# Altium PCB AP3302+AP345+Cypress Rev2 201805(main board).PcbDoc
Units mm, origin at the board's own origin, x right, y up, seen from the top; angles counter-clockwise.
Board outline 82.15 x 56.7 mm, 2 copper layers (Top Layer, Bottom Layer); 46 components, 60 nets, 128 pads, 78 vias.
Unrouted connection lines stored in the file: 2.
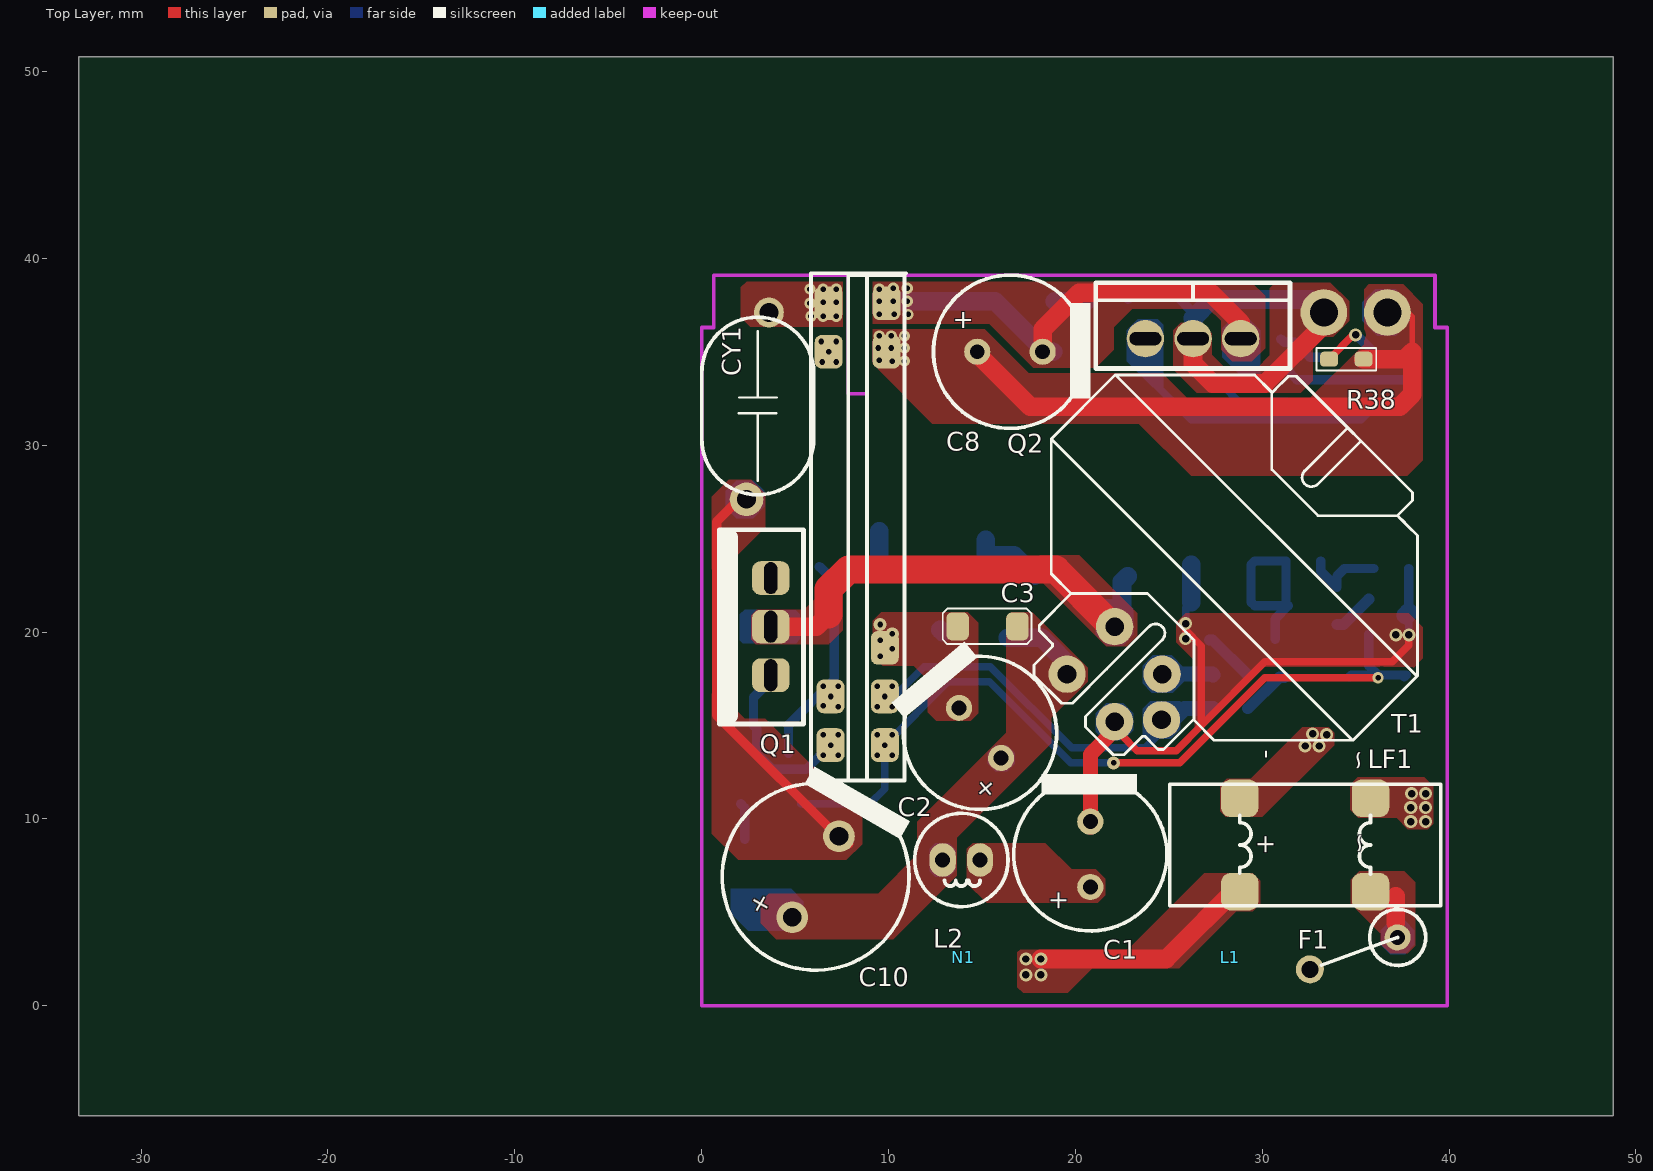
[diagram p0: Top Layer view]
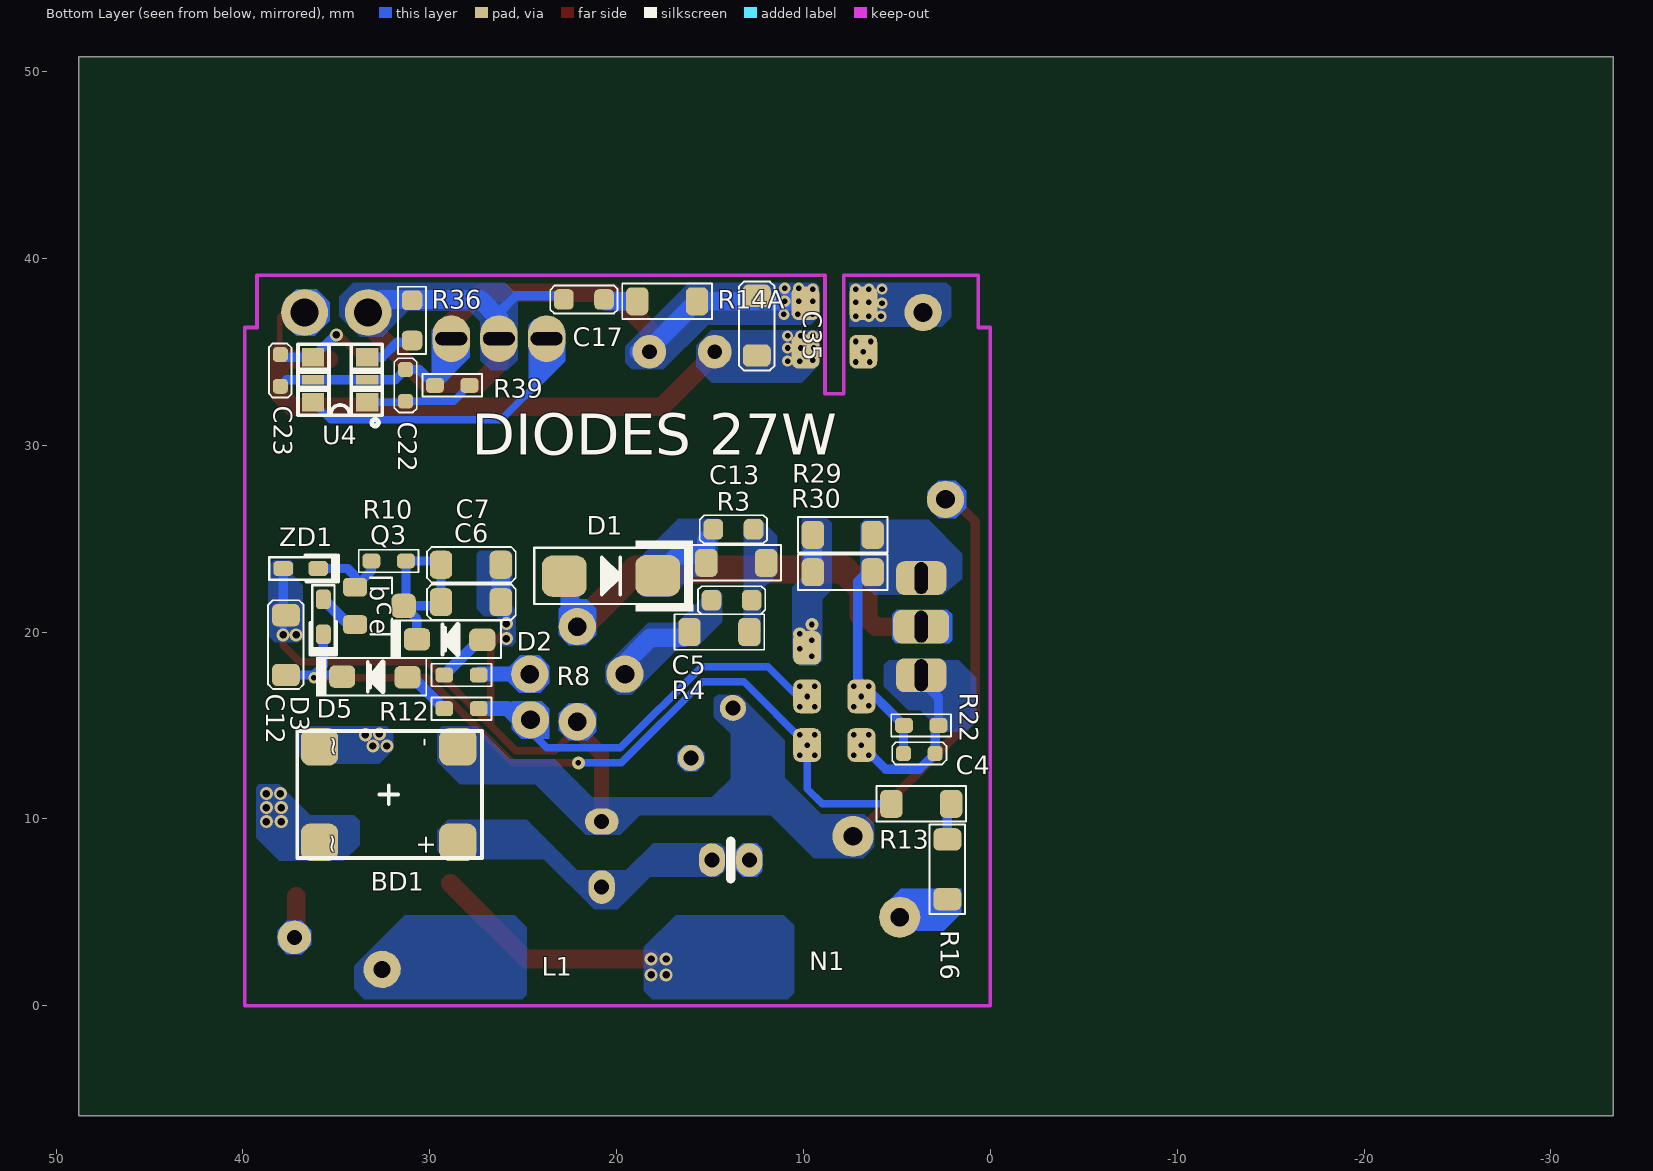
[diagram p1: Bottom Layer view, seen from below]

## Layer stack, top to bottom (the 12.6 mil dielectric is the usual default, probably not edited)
Top Layer: signal copper 0.0356
Dielectric: core 0.32, FR-4, Dk 4.8
Bottom Layer: signal copper 0.0356

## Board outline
-33.35,-5.9 -33.35,50.8 48.8,50.8 48.8,-5.9

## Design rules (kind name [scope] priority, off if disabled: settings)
Clearance [All] p1: gap=0.2
ComponentClearance [All] p1: gap=0.254 collisioncheckmode=3 verticalgap=0.254
PlaneConnect [All] p1: planeconnectstyle=Direct reliefexpansion=0.508 reliefentries=4 reliefconductorwidth=0.254 reliefairgap=0.254
PolygonConnect [All] p1: connectstyle=Direct reliefconductorwidth=0.254 reliefentries=4 polygonreliefangle="90 Angle"
RoomDefinition "AP3302+AP345+WT6615F Rev4 20170908(S2)updated" [InComponentClass('AP3302+AP345+WT6615F Rev4 20170908(S2)updated')] p1: confinementstyle=ConfineIn formatcopy=TRUE lockcomponents=FALSE outline -487.457,-410.573 -436.657,-410.573 -436.657,-385.173 -487.457,-385.173
RoutingVias [All] p1: holewidth=0.711 width=1.27 viastyle="Through Hole" minholewidth=0.711 minwidth=1.27 maxholewidth=0.711 maxwidth=1.27
SolderMaskExpansion [All] p1: expansion=0.102
TestPointUsage [All] p1: valid=0 allowmultiple=FALSE
Testpoint [(IsPad And (OnTopLayer Or OnBottomLayer))] p1: side=3 testpointundercomponent=TRUE minsize=1.016 maxsize=2.54 preferedsize=1.524 minholesize=0 maxholesize=1.016 preferedholesize=0.813 testpointgrid=0.025 style=297 order=0-112345678
Width [All] p1: maxlimit=3 minlimit=0.2 preferedwidth=0.3
17 further rules are at their usual default settings.

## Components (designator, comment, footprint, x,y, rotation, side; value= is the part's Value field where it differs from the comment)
BD1 "MSB30KH" BD-MSBL2A_6.7*7.4 32.2,11.3 r270 bottom
C1 "15uF/400V" EC-8X16-P3.5-C#1 20.8,8.1 r90 top
C2 "15uF/400V" EC-8X16-P3.5-C#2 14.9,14.6 r130 top
C3 "10nF/630V" 1206C(W) 15.3,20.3 r0 top
C4 "100pF/50V" 0603C(W) 3.8,13.5 r180 bottom
C5 "2.2nF/250V" 0805C(W) 13.9,21.7 r0 bottom
C6 "2.2uF/100V" 1206C(w) 27.8,21.6 r0 bottom
C7 "2.2uF/100V" 1206C(w) 27.8,23.6 r0 bottom
C8 "680uF/16V" EC-8X16-P3.5-C#3 16.5,35 r0 top
C10 "22uF/400V" EC-10X15-P5-C 6.1,6.9 r60 top (schematic designator C1)
C12 "4.7uF/50V" 1206C(W) 37.7,19.3 r270 bottom
C13 "2.2nF/250V" 0805C(W) 13.7,25.5 r180 bottom
C17 "1nF/200v" 0805c(W) 21.7,37.8 r180 bottom
C22 "22nF/50v" 0603c(w) 31.3,33.2 r270 bottom
C23 "100nF/50v" 0603C(W) 38,34 r90 bottom
C35 "10uF/16V" 1206C(w) 12.5,36.4 r90 bottom (schematic designator C7)
CY1 "470pF Y1" YC-9.5X6-P10 3,32.1 r270 top
D1 "RS1M" SMD-(DO-214AC/SMA) 20.3,23 r270 bottom
D2 "RS1MSWF" SMD-(SOD-123) 28.9,19.6 r180 bottom
D3 "1N4148WS" SMD-(SOD-523) 35.7,20.8 r90 bottom
D5 "RS1MSWF" SMD-(SOD-123) 32.9,17.6 r180 bottom
F1 "T2AL/250VAC" F-7.2X2.7-P5 34.9,2.8 r200 top
L1 "L" 22#单线打端子 28.3,2.6 r0 top
L2 "220uH" L-D5-P2 13.9,7.8 r180 top
LF1 "2mH" LF-14.5X6.5-P7X5 32.3,8.6 r180 top
N1 "N" 22#单线打端子 14,2.6 r0 top
Q1 "DMJ65H650SCTI" TO-220-T型槽 3.7,20.2 r180 top
Q2 "DMTH10H010LCT" TO-220(DH) 26.3,35.7 r180 top
Q3 "DMN24H3D" sot-23-1 32.6,21.4 r270 bottom
R3 "100K" 1206(W) 13.6,23.7 r0 bottom
R4 "100K" 1206(W) 14.5,20 r180 bottom
R8 "2R" 0603(W) 28.3,17.7 r180 bottom
R10 "100K" 0603(w) 32.2,23.8 r0 bottom
R12 "2R" 0603(W) 28.3,15.9 r0 bottom
R13 "1.8M" 1206(W) 3.7,10.8 r180 bottom
R14A "51R" 1206(w) 17.3,37.7 r0 bottom
R16 "1.8M" 1206(W) 2.3,7.3 r270 bottom
R22 "47K" 0603(W) 3.7,15 r180 bottom
R29 "0.82R" 1206(W) 7.9,25.2 r180 bottom
R30 "0.82R" 1206(W) 7.9,23.2 r180 bottom
R36 "10R" 0805(w) 31,36.6 r270 bottom
R38 "10R" 0603(W) 34.5,34.6 r180 top
R39 "51K" 0603(w) 28.8,33.2 r180 bottom
T1 "TRANS-RM8" TF-RM8(PIN6+2) 28.5,24 r45 top locked
U4 "APR345" SOT-23-6 34.8,33.5 r0 bottom
ZD1 "20V" SMD-(SOD-523) 36.9,23.4 r0 bottom

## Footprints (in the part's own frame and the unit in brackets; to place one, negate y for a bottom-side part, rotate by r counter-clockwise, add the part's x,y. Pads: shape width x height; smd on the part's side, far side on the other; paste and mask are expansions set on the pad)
22#单线打端子 [mm]
0603(W) [mm]
  rrect50% 0.95x0.8 smd mask+0.03: 1(-0.925,0) 2(0.925,0)
  silkscreen extent -1.6,-0.6 1.6,0.6, body extent -0.77,-0.42 0.78,0.43, height 0.45
0603(w) [mm]
  rrect50% 0.95x0.8 smd mask+0.03: 1(-0.925,0) 2(0.925,0)
  silkscreen extent -1.6,-0.6 1.6,0.6, body extent -0.77,-0.42 0.78,0.43, height 0.45
0603C(W) [mm]
  rrect50% 0.8x0.8 smd mask+0.03: 1(-0.85,0) 2(0.85,0)
  silkscreen extent -1.45,-0.6 1.45,0.6, body extent -0.8,-0.45 0.8,0.4, height 0.8
0603c(w) [mm]
  rrect50% 0.8x0.8 smd mask+0.03: 1(-0.85,0) 2(0.85,0)
  silkscreen extent -1.45,-0.6 1.45,0.6, body extent -0.8,-0.45 0.8,0.4, height 0.8
0805(w) [mm]
  rrect50% 1.05x1.1 smd mask+0.03: 1(-1.15,0.05) 2(1,0.05)
  silkscreen extent -1.88,-0.7 1.72,0.8, body extent -1.07,-0.57 0.93,0.68, height 0.45
0805C(W) [mm]
  rrect50% 1.05x1.1 smd mask+0.03: 1(-1.125,0) 2(1.025,0)
  silkscreen extent -1.85,-0.75 1.75,0.75, body extent -1.05,-0.62 0.95,0.63, height 0.6
0805c(W) [mm]
  rrect50% 1.05x1.1 smd mask+0.03: 1(-1.125,0) 2(1.025,0)
  silkscreen extent -1.85,-0.75 1.75,0.75, body extent -1.05,-0.62 0.95,0.63, height 0.6
1206(W) [mm]
  rrect50% 1.2x1.5 smd mask+0.03: 1(-1.6,0) 2(1.6,0)
  silkscreen extent -2.4,-0.95 2.4,0.95, body extent -1.6,-0.8 1.6,0.8, height 0.55
1206(w) [mm]
  rrect50% 1.2x1.5 smd mask+0.03: 1(-1.6,0) 2(1.6,0)
  silkscreen extent -2.4,-0.95 2.4,0.95, body extent -1.6,-0.8 1.6,0.8, height 0.55
1206C(W) [mm]
  rrect50% 1.2x1.5 smd mask+0.03: 1(-1.6,0) 2(1.6,0)
  silkscreen extent -2.4,-0.95 2.35,0.95, body extent -1.6,-0.8 1.6,0.8, height 0.79
1206C(w) [mm]
  rrect50% 1.2x1.5 smd mask+0.03: 1(-1.6,0) 2(1.6,0)
  silkscreen extent -2.4,-0.95 2.35,0.95, body extent -1.6,-0.8 1.6,0.8, height 0.79
BD-MSBL2A_6.7*7.4 [mm]
  rrect50% 2x2 smd: 1(2.55,3.7) 2(2.55,-3.7) 3(-2.55,-3.7) 4(-2.55,3.7)
  silkscreen extent -3.4,-4.9 3.4,5
EC-8X16-P3.5-C#1 [mm]
  round 1.4 / inner oval 1.8x1.4 / far side oval 1.8x1.4 hole 0.8: 1(-1.75,0)
  round 1.4 / inner oval 1.4x1.8 / far side oval 1.4x1.8 hole 0.8: 2(1.75,0)
  silkscreen extent -4.1,-4.1 4.3,4.1
EC-8X16-P3.5-C#2 [mm]
  round 1.4 hole 0.8: 1(-1.75,0) 2(1.75,0)
  silkscreen extent -4.1,-4.1 4.3,4.1
EC-8X16-P3.5-C#3 [mm]
  round 1.4 / inner round 1.8 / far side round 1.8 hole 0.8: 1(-1.75,0) 2(1.75,0)
  silkscreen extent -4.1,-4.1 4.3,4.1
EC-10X15-P5-C [mm]
  round 1.7 / inner round 2.2 / far side round 2.2 hole 1: 1(-2.5,0) 2(2.5,0)
  silkscreen extent -5,-5 5.1,5
F-7.2X2.7-P5 [mm]
  round 1.4 / inner round 1.8 / far side round 1.8 hole 0.8: 1(-2.5,0)
  round 1.5 / inner round 2 / far side round 2 hole 0.9: 2(2.5,0)
  silkscreen extent -4,-1.5 1.85,1.5
L-D5-P2 [mm]
  oval 1.4x1.8 hole 0.8: 1(-1,0) 2(1,0)
  silkscreen extent -2.5,-2.5 2.5,2.5
LF-14.5X6.5-P7X5 [mm]
  rrect50% 2x2 smd: 1(-3.5,2.5) 2(-3.5,-2.5) 3(3.5,-2.5) 4(3.5,2.5)
  silkscreen extent -7.25,-3.25 7.25,3.25
SMD-(DO-214AC/SMA) [mm]
  rrect50% 2.2x2.4 smd: 1(0.013,-2.5) 2(-0.013,2.5)
  silkscreen extent -1.9,-4.1 1.91,4.4
SMD-(SOD-123) [mm]
  rrect50% 1.4x1.2 smd mask+0.03: 1(1.71,-0.02) 2(-1.79,0.01)
  silkscreen extent -3.2,-1.04 2.71,1.06, body extent -1.89,-0.79 1.81,0.81, height 1.2
SMD-(SOD-523) [mm]
  rrect50% 1.05x0.8 smd: 1(0.95,0) 2(-0.925,0)
  silkscreen extent -2,-0.7 1.7,0.7
sot-23-1 [mm]
  rrect50% 1x1.3 smd: 1(-1,-1.4) 3(1,-1.4)
  rrect50% 1.3x1.3 smd: 2(0,1.2)
  silkscreen extent -1.5,-0.6 1.53,0.58
SOT-23-6 [mm]
  rect 1.2x1 smd: 1(-1.45,1.2) 3(-1.45,-1.2) 4(1.45,-1.2) 6(1.45,1.2)
  rect 1.2x0.5 smd: 2(-1.45,0) 5(1.45,0)
  silkscreen extent -2.3,-1.9 2.25,2.48
TF-RM8(PIN6+2) [mm]
  round 2 hole 1: 1(-10.75,1.9) 2(-10.75,-1.7) 4(-8.9,-3.4) 5(-7.15,1.9) 6(-7.15,-1.7)
  round 2.5 hole 1.5: 7(12.657,5.869) 8(15.061,3.465)
  silkscreen extent -12.05,-11.42 9.2,11.4
TO-220(DH) [mm]
  round 2 / inner oval 2x2.5 / far side oval 2x2.5 hole 0.7 slot 1.7 at 0 deg: 1(2.55,0) 2(0,0) 3(-2.55,0)
  silkscreen extent -5.19,-3 5.21,1.6
TO-220-T型槽 [mm]
  rrect50% 2x1.8 / inner rrect50% 2.7x1.8 / far side rrect50% 2.7x1.8 hole 0.7 slot 1.7 at 90 deg: 1(0,2.512) 3(0,-2.687)
  round 2 on Bottom Solder: 1(0,-3.537) 2(0.025,3.538)
  round 1 on Bottom Solder: 2(-1.4,-2.962) 5(1.397,-3.008) 6(-1.524,2.834) 10(1.524,2.834)
  rrect50% 2x1.8 / inner rrect50% 2x1.8 / far side rrect50% 3x1.8 hole 0.7 slot 1.7 at 90 deg: 2(0,-0.087)
  silkscreen extent -1.75,-5.28 2.75,5.12
YC-9.5X6-P10 [mm]
  round 1.6 / inner round 2 / far side round 2 hole 1: 1(-5,0.6)
  round 1.8 / inner round 2 / far side round 2 hole 1: 2(5,-0.6)
  silkscreen extent -4.75,-3 4.75,3

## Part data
BD1: library part BRIDGE, "Diode"
C1 C2 C10: library part "Cap Pol1", "Polarized Capacitor (Radial)"
C3 C4 C5 C6 C7 C12 C13 C23 C35 CY1: library part Cap, "Capacitor"
C8: library part CAPACITOR, "Capacitor"
C17 C22: library part CAP, "Capacitor"
D1 D2 D3 D5: library part D, "Diode"
F1: library part "Fuse 2", "Fuse"
L1 N1: library part CON1, "Connector"
L2: library part INDUCTOR, "inductor"
LF1: library part "INDUCTOR IRON"
Q1 Q2: library part "MOSFET N"
Q3: library part MOS-N2, "MOS"
R3 R4 R8 R10 R12 R13 R16 R22 R29 R30: library part Res3, "Resistor"
R14A R36 R38 R39: library part RES2
T1: library part TRANS_RM7, "transformer"
U4: library part AP345
ZD1: library part ZD, "Zener Diode"

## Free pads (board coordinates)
  rrect50% 1.5x1.8 smd: 5(6.8,35) 5(6.8,37.6) 5(6.9,16.55) 5(6.9,13.95) 5(9.8,13.95) 5(9.8,16.55) 5(9.8,19.15) 5(9.9,35) 5(9.9,37.6)
  rrect50% 1.5x1.8 smd far side: 5(6.8,35) 5(6.8,37.6) 5(6.9,13.95) 5(6.9,16.55) 5(9.8,13.95) 5(9.8,16.55) 5(9.8,19.15) 5(9.9,35) 5(9.9,37.6)

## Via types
v1: diameter 0.6, hole 0.3, Top Layer to Bottom Layer, 53 vias
v2: diameter 0.7, hole 0.4, Top Layer to Bottom Layer, 19 vias
v3: diameter 0.7, hole 0.3, Top Layer to Bottom Layer, 6 vias

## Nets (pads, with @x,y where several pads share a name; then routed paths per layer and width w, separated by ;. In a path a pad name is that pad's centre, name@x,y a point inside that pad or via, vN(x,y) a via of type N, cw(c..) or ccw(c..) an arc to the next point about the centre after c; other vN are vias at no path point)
CC1: 
CC2: 
D+: 
D-: 
EARTH: 
GND: BD1.4 C1.2 C2.2 C3.1 C6.1 C7.1 C10.2 C12.1 CY1.2 pad.5@9.8,19.15 R29.1 R30.1 T1.2 ZD1.1 | length 62.6
  Top Layer w0.4: T1.2@22.401,15.297 T1.2@22.501,15.397 ; T1.2@22.501,14.449 23.3,13.65 25.395,13.65 26.75,15.005 ; v2(25.9,20.45) 25.9,20.1 26.75,19.25 26.75,15.005 ; v2(37.85,19.85) 37.85,19.3 36.95,18.4 30.145,18.4 26.75,15.005
  Top Layer w0.5: CY1.2@2.4,27.5 0.8,25.9 0.8,15.55 7.682,8.668 C10.2@7.868,8.668
  Top Layer w0.8: C1.2@20.8,9.55 20.8,13.45 22.501,15.151 T1.2@22.501,15.197
  Bottom Layer w0.4: v2(25.9,20.45) 25.9,21.3 C6.1 ; C12.1 37.85,20.75 v2(37.85,19.85)
  Bottom Layer w0.5: C12.1@37.85,21.05 37.85,22.1 ZD1.1
  Bottom Layer w1: CY1.2@2.4,27.5 CY1.2@2.65,27.25 ; R30.1@9.5,23.5 R29.1@9.5,25.4 ; C6.1 C7.1 ; C12.1 C12.1@37.85,21.05
  other v2: 25.9,19.65 37.15,19.85
  other v3: 9.55,18.7 10.2,19.1 9.55,19.55 10.2,19.9 9.55,20.4
NetBD1_1: BD1.1 C1.1 L2.1 | length 0.1
  Top Layer w0.5: L2.1@14.783,7.8 L2.1
NetBD1_2: BD1.2 LF1.2
  other v2: 37.95,9.85 38.75,9.85 37.95,10.6 38.75,10.6 38,11.35 38.75,11.35
NetBD1_3: BD1.3 LF1.3
  other v2: 32.3,13.9 33.05,13.9 33.45,14.5 32.7,14.55
NetC2_1: C2.1 C3.2 C5.2 C10.1 L2.2 R4.1 R16.2 T1.1 | length 4.6
  Bottom Layer w0.254: T1.1@19.4,17.9 T1.1@19.75,17.9
  Bottom Layer w1: R4.1@16.4,19.7 18.197,19.7 T1.1@19.955,17.942
NetC4_1: C4.1 pad.5@6.9,16.55 Q1.3 R22.1 R29.2 R30.2 | length 11.4
  Bottom Layer w0.5: C4.1 4.65,14.975 R22.1 7.1,17.475 7.1,22.7 R30.2@6.3,23.5
  other v1: 7.3,16 6.5,16.05 6.9,16.55 6.5,17.1 7.3,17.1
NetC4_2: C4.2 pad.5@6.9,13.95 Q1.1@3.7,17.688 R22.2 | length 9.7
  Bottom Layer w0.5: Q1.1@3.962,17.688 3.7,17.688 3.7,17.425 2.775,16.5 R22.2 2.95,14.825 C4.2 3.8,12.65 5.6,12.65 v1(6.9,13.95)
  other v1: 6.5,13.4 7.3,13.4 6.5,14.5 7.3,14.5
NetC5_1: C5.1 C13.2 R3.1 R4.2 | length 0.2
  Bottom Layer w1: R4.2@12.775,20.125 R4.2
NetC6_2: C6.2 C7.2 D2.2 Q3.2 R10.1 | length 10.6
  Bottom Layer w0.5: D2.2 30.69,20.69 Q3.2 ; Q3.2 31.275,21.525 R10.1 29.6,23.8 C7.2 C6.2 29.6,21.4 Q3.2
NetC13_1: C13.1 D1.2 R3.2 | length 3.9
  Bottom Layer w1: 15.2,24.925 15.2,24.1 16.713,24.1 D1.2
NetC15_1: 
NetC15_2: 
NetC16_1: 
NetC16_2: 
NetC17_1: C17.1 Q2.2 R36.1 T1.7 | length 23.8
  Top Layer w1: Q2.2@26.3,35.5 26.3,34.35 27.35,33.3 30.15,33.3 33.3,36.45 T1.7
  Bottom Layer w0.5: C17.1 23.025,38 25.4,38 26.3,37.1 26.3,36.8 Q2.2@26.3,35.5
  Bottom Layer w1: Q2.2@26.3,36.8 27.3,37.8 32.6,37.8 T1.7
NetC17_2: C17.2 R14A.2 | length 2.1
  Bottom Layer w0.4: C17.2 C17.2@20.9,37.575
  Bottom Layer w1: R14A.2 20.575,37.7 C17.2
NetC18_1: 
NetC19_2: 
NetC22_2: C22.2 R39.2 U4.1 | length 5.9
  Bottom Layer w0.4: R39.2@27.97,33.2 R39.2 28.725,32.35 C22.2 31.35,32.3 U4.1
NetC23_2: C23.2 R38.2 U4.4 | length 5.4
  Top Layer w0.4: R38.2 v2@34.875,35.9
  Bottom Layer w0.5: v2(35,35.9) 35.05,35.9 U4.4 37.85,34.7 C23.2
NetC24_2: 
NetC26_2: 
NetC28_1: 
NetC29_2: 
NetC30_2: 
NetC31_2: 
NetD1_1: D1.1 Q1.2@3.7,20.287 T1.5 | length 24
  Top Layer w1: Q1.2@3.7,20.287 6.137,20.287 6.8,20.95
  Top Layer w1.5: 6.8,20.95 6.8,22.3 7.85,23.35 18.95,23.35 T1.5@21.812,20.488
  Bottom Layer w1: T1.5@22.501,20.488 22.501,22.688 D1.1
NetD2_1: D2.1 R8.1 | length 2.8
  Bottom Layer w0.6: D2.1 27.345,19.58 R8.1
NetD3_1: D3.1 Q3.3 | length 2.3
  Bottom Layer w0.6: Q3.3 34.35,20.4 D3.1
NetD4_2: 
NetD5_1: D5.1 R12.2 | length 2.7
  Bottom Layer w0.6: R12.2 29.247,15.9 30.927,17.58 D5.1
NetD6_1: 
NetD6_2: 
NetF1_1: F1.1 LF1.1 | length 1.4
  Top Layer w1: 37.148,4.434 37.148,5.852
NetF1_2: F1.2
NetLF1_4: LF1.4 | length 12.4
  Top Layer w1: v2(18.15,2.5) 24.85,2.5 LF1.4@28.9,6.55
  other v2: 17.35,1.65 18.15,1.65 17.35,2.5
NetNTC1_1: 
NetNTC2_1: 
NetQ2_1: Q2.1 U4.6 | length 15.6
  Bottom Layer w0.4: Q2.1@23.75,35.5 23.75,33.8 26.19,31.36 35.31,31.36 U4.6
NetQ3_1: Q3.1 R10.2 ZD1.2 | length 4.5
  Bottom Layer w0.5: R10.2 33.125,23.275 Q3.1 34,23 34.4,23.4 ZD1.2
NetQ4_1: 
NetQ4_4: 
NetR1_2: 
NetR8_2: R8.2 T1.6 | length 2.7
  Bottom Layer w0.8: T1.6 27.333,17.742 R8.2
NetR12_1: pad.5@9.8,16.55 R12.1 T1.4 | length 20.9
  Bottom Layer w0.4: v1(9.8,16.55) 10.3,16.55 11.9,18.15 15.45,18.15 19.803,13.797 23.744,13.797 T1.4@25.25,15.303
  Bottom Layer w0.8: T1.4@25.25,15.303 25.847,15.9 R12.1
  other v1: 9.4,16 10.2,16 9.4,17.1 10.2,17.1
NetR13_2: R13.2 R16.1 | length 2
  Bottom Layer w0.5: R13.2 2.3,10.6 R16.1
NetR18_2: 
NetR25_2: 
NetR27_1: 
NetR31_2: 
NetR36_2: R36.2 U4.3 | length 2.8
  Bottom Layer w0.5: R36.2@31,35.675 31.175,35.5 31.75,35.5 32.55,34.7 U4.3
OP+: C8.1 C35.1 pad.5@6.8,35 pad.5@9.9,35 R38.1 T1.8 | length 32.3
  Top Layer w0.3: T1.8@37.6,37.3 38.025,36.875 38.025,35
  Top Layer w1: C8.1@14.7,34.95 17.59,32.06 37.36,32.06 38.025,32.725 38.025,35 37.625,34.6 R38.1
  other v1: 6.45,34.45 7.2,34.45 10.2,34.5 10.85,34.5 9.5,34.55 6.8,35 9.45,35.2 10.15,35.2 10.85,35.2 6.4,35.55 7.2,35.55 9.5,35.85 10.15,35.85 10.85,35.85
SGND: C8.2 C22.1 C23.1 C35.2 CY1.1 pad.5@6.8,37.6 pad.5@9.9,37.6 Q2.3 R14A.1 R39.1 U4.2 U4.5 | length 35.5
  Top Layer w1: C8.2 18.25,36.2 20.2,38.15 27.25,38.15 28.85,36.55 Q2.3@28.85,35.9
  Bottom Layer w0.5: Q2.3@28.85,35.5 29.1,35.25 29.1,33.825 R39.1 30.575,34.05 C22.1 31.85,33.5 U4.2 U4.5 37.65,33.5 C23.1
  Bottom Layer w1: pad.5@10.1,37.7 R14A.1 18.25,35.15 C8.2 C8.2@18.8,35
  other v1: 5.85,36.9 6.5,36.9 7.2,36.9 9.5,37 10.3,37 11.05,37 5.8,37.6 6.5,37.65 7.2,37.65 9.5,37.7 10.25,37.7 11,37.7 5.8,38.35 6.5,38.35 7.2,38.35 9.5,38.35 10.25,38.4 11,38.4
VCC: C12.2 D3.2 D5.2 pad.5@9.8,13.95 R13.1 | length 44.2
  Top Layer w0.4: v3(22.05,13) 25.593,13 30.143,17.55 v1(36.2,17.55)
  Bottom Layer w0.4: R13.1 9,10.8 9.8,11.6 v1(9.8,13.95) 13.2,17.35 15.401,17.35 19.751,13 v3(22.05,13)
  Bottom Layer w0.5: D5.2 34.78,17.7 v1@36.2,17.7 ; D3.2 35.7,18.2 v1@36.2,17.7 ; C12.2@37.61,17.61 C12.2 v1@36.2,17.7
  other v1: 9.4,13.4 10.2,13.4 9.4,14.5 10.2,14.5
VOUT: 
pads on no net: Q1.1@3.7,23.737 Q1.2@3.675,16.662 Q1.2@5.1,23.162 Q1.5 Q1.6 Q1.10

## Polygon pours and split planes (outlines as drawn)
SGND on Top Layer "MidLayer2-No Net" (solid, remove dead copper, pour order 1000): 9.1,38.75 24,38.75 24,38.25 22.05,36.323 22.05,35.1 21.1,34.15 17.75,34.15 15.4,36.5 9.1,36.5
OP+ on Top Layer "MidLayer2-No Net" (solid, remove dead copper, pour order 1001): 35.7,38.6 37.55,38.6 38.6,37.55 38.6,29.2 37.75,28.35 26.2,28.35 23.4,31.15 12.35,31.15 9.1,34.4 9.1,36.2 15.15,36.2 17.5,33.85 24.65,33.85 26.1,32.4 32.45,32.4 35.45,35.4 35.45,38.35
NetC2_1 on Top Layer "Top Layer-No Net" (solid, pour order 1004): 4,3.55 10.25,3.55 13.65,6.95 13.65,9 18.7,14.05 18.7,15.4 20.65,17.35 20.65,18.1 17.7,21.05 16.55,21.05 16.3,20.8 16.3,14.6 11.55,9.85 11.55,8.1 9.45,6 3.6,6 3.15,5.55 3.15,4.4
NetD1_1 on Top Layer "MidLayer2-No Net" (solid, remove dead copper, pour order 1001): 17.85,23.85 18.1,24.1 20.2,24.1 23.3,21 23.3,19.8 22.75,19.25 21.65,19.25 17.85,23.05
SGND on Top Layer "MidLayer2-No Net" (solid, remove dead copper, pour order 1004): 29.4,38.75 30.15,38 30.15,35.2 29.45,34.5 28.4,34.5 27.8,35.1 27.8,36.65 27.15,37.3 22.1,37.3 22.1,38.7 22.15,38.75
NetD1_1 on Top Layer "MidLayer2-No Net" (solid, remove dead copper, pour order 1002): 5.5,21.2 6.7,22.4 7.55,22.4 7.55,20.1 6.8,19.35 2.9,19.35 2.65,19.6 2.65,20.9 2.95,21.2
SGND on Top Layer "MidLayer2-No Net" (solid, remove dead copper, pour order 1002): 7.6,38.75 7.6,36.35 2.6,36.35 2.1,36.85 2.1,38.45 2.4,38.75
NetBD1_3 on Top Layer "Top Layer-No Net" (solid, pour order 1005): 28.05,10.1 30,10.1 33.85,13.95 33.85,14.6 33.55,14.9 32.15,14.9 29.4,12.15 28.1,12.15 27.75,11.8 27.75,10.4
NetLF1_4 on Top Layer "Top Layer-No Net" (solid, pour order 1002): 17.2,0.7 19.6,0.7 20.9,2 25.55,2 28.6,5.05 29.5,5.05 29.9,5.45 29.9,6.7 29.5,7.1 26.9,7.1 22.8,3 17.05,3 16.9,2.85 16.9,1
NetF1_1 on Top Layer "Top Layer-No Net" (solid, pour order 1000): 34.75,6.75 34.75,5.45 36.35,3.85 36.35,3.3 36.85,2.8 37.8,2.8 38.2,3.2 38.2,6.6 37.6,7.2 35.2,7.2
NetBD1_2 on Top Layer "Top Layer-No Net" (solid, pour order 1001): 35.125,12.225 38.675,12.225 39.15,11.75 39.15,9.75 38.85,9.45 37.8,9.45 37.2,10.05 35.15,10.05 34.725,10.475 34.725,11.825
NetC17_1 on Top Layer "MidLayer2-No Net" (solid, remove dead copper, pour order 1005): 30.7,38.7 33.65,38.7 34.65,37.7 34.65,36.65 33.8,35.8 33.35,35.8 32.7,35.15 32.7,33.45 32.05,32.8 26.5,32.8 25.25,34.05 25.25,36.15 25.65,36.55 26.75,36.55 27.3,36 27.3,34.85 28.05,34.1 29.7,34.1 30.4,34.8 30.4,38.4
NetBD1_1 on Top Layer "Top Layer-No Net" (solid, pour order 1000): 14.5,8.7 18.4,8.7 19.8,7.3 21.1,7.3 21.6,6.8 21.6,5.9 21.2,5.5 15.25,5.5 14.2,6.55 14.2,8.4
GND on Top Layer "MidLayer2-No Net" (solid, remove dead copper, pour order 1000): 25.9,21 37.85,21 38.6,20.25 38.6,18.6 38.1,18.1 38.05,18.15 29.895,18.15 27.095,15.35 26.4,14.65 26.4,18.45 25.4,19.45 25.4,20.5
GND on Top Layer "MidLayer2-No Net" (solid, remove dead copper, pour order 1007): 1.45,28.15 2.65,28.15 3.4,27.4 3.4,25.6 1.15,23.35 0.55,23.35 0.55,27.25
GND on Top Layer "MidLayer2-No Net" (solid, remove dead copper, pour order 1006): 7.75,7.8 8.6,8.65 8.6,10.15 3.4,15.35 2.3,15.35 0.95,16.7 0.55,16.7 0.55,9.2 1.95,7.8
GND on Top Layer "Top Layer-No Net" (solid, pour order 1006): 12.1,17.45 12.1,15.7 12.55,15.25 14.4,15.25 14.8,15.65 14.8,20.5 14.25,21.05 9.6,21.05 9.15,20.6 9.15,18.75 9.7,18.2 11.35,18.2
SGND on Bottom Layer "MidLayer2-No Net" (solid, remove dead copper, pour order 1003): 16.15,38.7 19.55,35.3 19.55,34.4 19.2,34.05 17.5,34.05 15.1,36.45 9.6,36.45 9.05,37 9.05,38.4 9.35,38.7
OP+ on Bottom Layer "MidLayer2-No Net" (solid, remove dead copper, pour order 1005): 14.95,36.15 15.75,35.35 15.75,34.2 14.9,33.35 10.1,33.35 9.1,34.35 9.1,36.15
NetF1_2 on Bottom Layer "Top Layer-No Net" (solid, pour order 1007): 25.05,0.35 33.5,0.35 34.05,0.9 34.05,2.15 31.35,4.85 25.45,4.85 24.8,4.2 24.8,0.6
NetLF1_4 on Bottom Layer "Top Layer-No Net" (solid, pour order 1009): 10.85,0.35 18.1,0.35 18.55,0.8 18.55,3.15 16.85,4.85 11.05,4.85 10.5,4.3 10.5,0.7
NetC4_2 on Bottom Layer "MidLayer2-No Net" (solid, remove dead copper, pour order 1000): 1.7,18.5 5.45,18.5 5.7,18.25 5.7,17.1 4.4,15.8 3.75,15.8 2.6,14.65 1.3,14.65 0.75,15.2 0.75,17.55
NetC2_1 on Bottom Layer "Top Layer-No Net" (solid, pour order 1003): 14.35,22.05 14.35,20.55 15.65,19.25 16.6,19.25 19.2,16.65 19.95,16.65 20.6,17.3 20.6,18.2 18.3,20.5 16.75,20.5 15,22.25 14.55,22.25
GND on Bottom Layer "Top Layer-No Net" (solid, pour order 1015): 29.6,14.7 29.6,13.05 28.4,11.85 24.35,11.85 21.65,9.15 19.8,9.15 18.75,10.2 11.75,10.2 9.45,7.9 6.8,7.9 6.2,8.5 6.2,9.7 6.75,10.25 9.05,10.25 11,12.2 11,14.2 13.45,16.65 14.6,16.65 14.8,16.45 14.8,15.45 13.9,14.55 13.9,12.15 14.9,11.15 21.3,11.15 23.35,13.2 25.75,13.2 27.5,14.95 29.35,14.95
NetC17_1 on Bottom Layer "MidLayer2-No Net" (solid, remove dead copper, pour order 1008): 25.3,38 26,38.7 34.1,38.7 34.85,37.95 34.85,36.9 33.75,35.8 32.55,35.8 31.15,37.2 27.9,37.2 27.3,36.6 27.3,34.55 26.75,34 25.85,34 25.3,34.55
GND on Bottom Layer "MidLayer2-No Net" (solid, remove dead copper, pour order 1003): 8.8,26.15 10.05,26.15 10.1,26.1 10.1,22.9 10.6,22.4 10.6,18.6 10.2,18.2 9.3,18.2 9,18.5 9,21.75 8.5,22.25 8.5,25.85
NetC4_1 on Bottom Layer "Top Layer-No Net" (solid, pour order 1017): 6.95,22.618 6.95,25.8 6.75,26 3.3,26 1.5,24.2 1.5,22.85 2.552,22 6.185,22
SGND on Bottom Layer "MidLayer2-No Net" (solid, remove dead copper, pour order 1004): 7.6,38.7 7.6,36.35 2.6,36.35 2.1,36.85 2.1,38.45 2.35,38.7
NetBD1_1 on Bottom Layer "Top Layer-No Net" (solid, pour order 1013): 14.45,8.7 18.05,8.7 19.5,7.25 22.1,7.25 24.8,9.95 29.05,9.95 29.6,9.4 29.6,8.3 29.15,7.85 23.9,7.85 21.2,5.15 19.95,5.15 18.2,6.9 14.55,6.9 14.2,7.25 14.2,8.45
GND on Bottom Layer "MidLayer2-No Net" (solid, remove dead copper, pour order 1004): 25.75,24.35 27.35,24.35 27.5,24.2 27.5,21.25 27.1,20.85 26.45,20.85 26.25,20.65 26.25,19.4 26.1,19.25 25.6,19.25 25.4,19.45 25.4,21.2 25.6,21.4 25.6,24.2
GND on Bottom Layer "MidLayer2-No Net" (solid, remove dead copper, pour order 1003): 37.45,23.85 38.35,23.85 38.65,23.55 38.65,19.8 38.3,19.45 37,19.45 36.8,19.65 36.8,22.5 37.3,23 37.3,23.7
NetBD1_2 on Bottom Layer "Top Layer-No Net" (solid, pour order 1008): 34.6,7.75 38.05,7.75 39.3,9 39.3,11.7 39.15,11.85 38.05,11.85 36.4,10.2 34.05,10.2 33.75,9.9 33.75,8.6
NetBD1_3 on Bottom Layer "Top Layer-No Net" (solid, pour order 1010): 36.6,12.95 32.7,12.95 31.95,13.7 31.95,14.6 32.3,14.95 36.6,14.95 37.05,14.5 37.05,13.4
NetC5_1 on Bottom Layer "Top Layer-No Net" (solid, pour order 1001): 13.2,25.8 13.2,19.25 12.45,19.25 12.3,19.4 12.3,22.2 11.4,23.1 11.4,25.15 12.25,26 12.3,26.05 12.95,26.05
NetC13_1 on Bottom Layer "Top Layer-No Net" (solid, pour order 1002): 14.6,26.05 16.7,26.05 18.95,23.8 18.95,22.25 18.6,21.9 17.05,21.9 16,22.95 14.85,22.95 14.6,23.2

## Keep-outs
Keep-Out Layer:
  lines w0.2: 10.7,39.1 8.85,39.1 ; 8.85,39.1 8.85,32.75 7.85,32.75 7.85,39.1 0.65,39.1 0.65,36.3 0,36.3 0,0 39.9,0 39.9,36.3 39.25,36.3 39.25,39.1 8.85,39.1

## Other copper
Bottom Layer:
  region net NetQ2_1: 22.75,36.15 22.75,34.5 24.15,33.1 24.7,33.1 24.7,36.45 24.4,36.75 23.35,36.75
  region net SGND: 27.85,36.25 27.85,34.7 29.6,32.95 29.9,32.95 29.9,36.15 29.3,36.75 28.35,36.75
  region net OP+: 36.15,35.85 37.15,35.85 37.85,36.55 37.85,37.65 37.15,38.35 36.05,38.35 35.35,37.65 35.35,36.65
  region net GND: 1.85,26.1 2.75,26.1 3.35,26.7 3.35,27.55 2.8,28.1 1.85,28.1 1.3,27.55 1.3,26.65
  region net NetD1_1: 2.2,19.4 5.05,19.4 5.25,19.6 5.25,20.95 5,21.2 2.3,21.2 2.05,20.95 2.05,19.55
  region net NetC2_1: 12.5,6.9 13.25,6.9 13.6,7.25 13.6,8.35 13.25,8.7 12.5,8.7 12.2,8.4 12.2,7.2
  region net NetC2_1: 15.7,12.55 16.35,12.55 16.75,12.95 16.75,13.55 16.35,13.95 15.7,13.95 15.3,13.55 15.3,12.95
  region net NetF1_1: 36.85,2.75 37.65,2.75 38.15,3.25 38.15,4.05 37.65,4.55 36.85,4.55 36.35,4.05 36.35,3.25
  region net GND: 21.55,14.2 22.55,14.2 23.1,14.75 23.1,15.65 22.55,16.2 21.65,16.2 21.1,15.65 21.1,14.65
  region net NetR12_1: 23.607,14.299 25.099,14.299 25.601,14.801 25.601,16.301 24.001,16.301 23.601,15.901
  region net NetR8_2: 24.1,16.75 25.2,16.75 25.8,17.35 25.8,18.1 25.15,18.75 24.15,18.75 23.6,18.2 23.6,17.25
  region net NetD1_1: 21.65,19.3 22.55,19.3 23.1,19.85 23.1,21.25 22.6,21.75 21.6,21.75 21.1,21.25 21.1,19.85
  region net NetC2_1: 1.55,6.25 4.8,6.25 5.45,5.6 5.45,4.65 4.8,4 2.5,4 1.55,4.95

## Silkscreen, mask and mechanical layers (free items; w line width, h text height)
Top Overlay:
  lines w0.2: 10.35,39.15 8.85,39.15 8.85,12.05 ; 10.85,12.05 8.85,12.05 ; 10.85,12.1 10.85,39.1 7.85,39.1 7.85,12.05 ; 10.95,39.2 5.85,39.2 5.85,12.05 7.85,12.05 ; 7.85,12.05 8.85,12.05
Bottom Overlay:
  text "DIODES 27W" at 27.75,29.5 h2.2
Bottom Solder:
  rectangle: 29.85,0.55 31,3.85
  rectangle: 28.2,0.55 29.35,3.85
  rectangle: 26.55,0.55 27.7,3.85
  rectangle: 24.95,0.5 26.1,3.8
  rectangle: 15.5,0.55 16.65,3.8
  rectangle: 13.9,0.5 15.05,3.8
  rectangle: 12.25,0.5 13.4,3.75
  rectangle: 10.6,0.5 11.75,3.75
Mechanical 1:
  lines w0.2: 7.85,11.65 7.85,21.45 8.85,21.45 8.85,11.65 7.85,11.65
Mechanical 2:
  circle w0.1: c12.2,22.6 r0.75
  circle w0.01: c17.25,14.4 r0.75
  circle w0.01: c18.9,16.5 r0.75
  circle w0.1: c16,27.55 r3.4
  lines w0.1: 0,2 39.85,2 ; 0.651,39.1 0.651,36.3 0.002,36.3 0.002,0 39.95,0 ; 0.945,0 0.945,39.1 ; 4.318,0 4.317,39.1 ; 6.041,0 6.041,1.5 7.041,1.5 7.041,0 ; 10.241,0 10.241,4.7 10.241,5 17.693,5 17.693,4.7 17.735,0 ; 10.691,32.524 10.691,44.51 ; 13.918,-4 13.918,6.67 ; 19.945,-4.127 19.945,43.083 ; 24.545,0 24.545,4.7 24.545,5 31.95,5 31.95,4.7 31.95,0 ; 28.251,-3.956 28.251,6.714 ; 35.569,0 35.569,39.1 ; 38.845,0 38.845,39.1 ; 39.24,39.1 39.24,36.3 39.888,36.3 39.888,0
  lines w0.2: -10.75,24.1 10.25,24.1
